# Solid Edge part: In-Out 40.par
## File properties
Title: In - Out 40
Author: DESYS
Template: Normal.par
Last saved by: s.pallini
Revision: 8
Application: Solid Edge
Tipo di contenuto documento: 0
Precisione: 0,99
Document Number: 8021
Revision: 0
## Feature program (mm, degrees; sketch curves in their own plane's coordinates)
sketch for "unnamed RevolvedProtrusion 1" plane through (0, 0, 0) normal (0, -1, 0) x-axis (1, 0, 0)
  line (-197.5, 42.4462) -> (-197.5, 40.4462)
  arc centre (-192.5, 40.4462) radius 5 from (-197.5, 40.4462) to (-192.5, 35.4462) ccw
  line (-192.5, 35.4462) -> (-188.2906, 35.4462)
  arc centre (-188.2906, 29.4462) radius 6 from (-182.2984, 29.753) to (-188.2906, 35.4462) ccw
  arc centre (-32.4945, 37.4215) radius 150 from (-182.2984, 29.753) to (-95.7809, -98.5743) ccw
  arc centre (-100, -107.6406) radius 10 from (-90, -107.6406) to (-95.7809, -98.5743) ccw
  line (-90, -123.5538) -> (-90, -107.6406)
  arc centre (-84, -123.5538) radius 6 from (-90, -123.5538) to (-84, -129.5538) ccw
  line (-28, -129.5538) -> (-84, -129.5538)
  arc centre (-28, -126.5538) radius 3 from (-28, -129.5538) to (-25, -126.5538) ccw
  line (-25, -97.9129) -> (-25, -126.5538)
  arc centre (-35, -97.9129) radius 10 from (-25, -97.9129) to (-31.4786, -88.5535) ccw
  arc centre (49.5128, 126.7147) radius 230 from (-165.1148, 44.0408) to (-31.4786, -88.5535) ccw
  arc centre (-174.4464, 40.4462) radius 10 from (-165.1148, 44.0408) to (-174.4464, 50.4462) ccw
  line (-189.5, 50.4462) -> (-174.4464, 50.4462)
  arc centre (-189.5, 42.4462) radius 8 from (-197.5, 42.4462) to (-189.5, 50.4462) cw
  dimension (linear) = 90
revolve "unnamed RevolvedProtrusion 1" add full turn 360 deg
sketch for "ExtrudedCutout_1" #1 plane through (0, 0, -129.5538) normal (0, 0, -1) x-axis (1, 0, 0)
  line (6.99, 34.2949) -> (13.4808, 66.1401)
  arc centre (0, 0) radius 67.5 from (13.4808, 66.1401) to (13.4808, -66.1401) cw
  line (6.99, -34.2949) -> (13.4808, -66.1401)
  arc centre (0, 0) radius 35 from (6.99, 34.2949) to (6.99, -34.2949) cw
sketch for "ExtrudedCutout_1" #2 plane through (0, 0, -129.5538) normal (0, 0, -1) x-axis (1, 0, 0)
  line (-6.99, 34.2949) -> (-13.4808, 66.1401)
  line (-6.99, -34.2949) -> (-13.4808, -66.1401)
extrude "ExtrudedCutout_1" cut finite 30 along -normal  Treatment1_DraftAngle = 15 deg
fillet "Rotondo_1" radius 6
sketch for "Foro_1" plane through (0, 0, 0) normal (0, -1, 0) x-axis (1, 0, 0)
  hole centre (0, -9.5538) bore radius 10
hole "Foro_1" diameter 20 finite
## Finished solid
Body 1: solid body, 65 faces, 116 edges, 53 vertices.
  Faces by surface: torus 18, blend 14, cylinder 12, plane 10, sphere 7, cone 4
  Edges by curve: circle 68, intersection 32, line 16
Bounding box of the edges (mm; curved faces can reach further): 395.000 x 395.000 x 180.000, from (-197.5, -197.5, -129.5538) to (197.5, 197.5, 50.4462).
Cylindrical faces by radius (mm): R6 x8, R10 x1, R25 x1, R90 x1, R197.5 x1
Conical faces (half-angle, radius in mm at the cone's reference point): 15 deg R35 x2, 15 deg R67.5 x2
Toroidal faces (ring radius, tube radius in mm): R-49.5128 r230 x1, R28 r3 x1, R30.396 r6 x2, R32.4945 r150 x1, R35 r10 x1, R47.6424 r6 x2, R54.8576 r6 x2, R72.104 r6 x2, R84 r6 x1, R100 r10 x1, R174.4464 r10 x1, R188.2906 r6 x1, R189.5 r8 x1, R192.5 r5 x1
Spherical faces by radius (mm): R6 x7
Planar faces by outward normal: +z 1, -y 1, -z 4, oblique 4
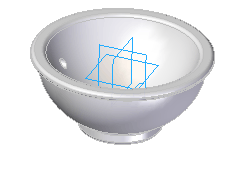
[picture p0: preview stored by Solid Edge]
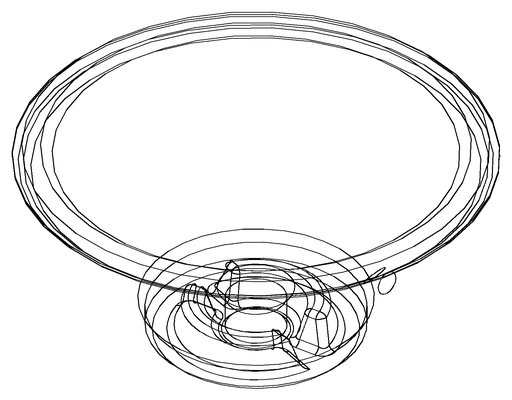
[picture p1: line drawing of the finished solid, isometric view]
